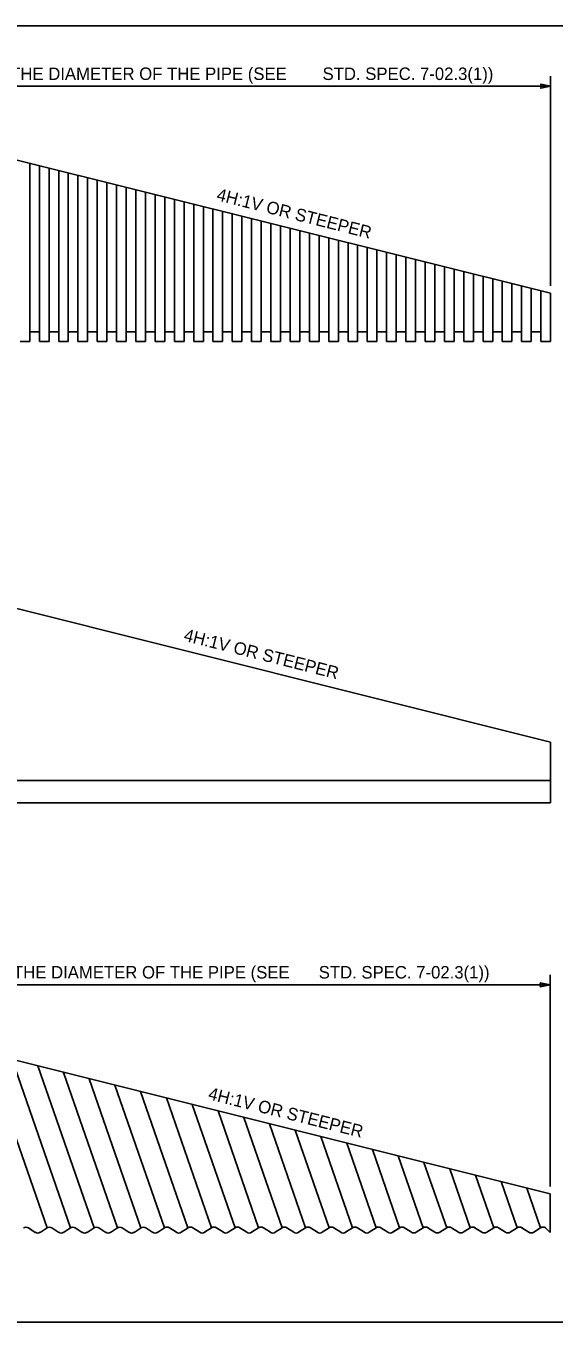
# Model space of a CAD drawing. Extents: x 99862 to 103680, y 99470 to 102076.
# Drawn here: x 101176 to 102021, y 100000 to 102076 of the extents above; entities that cross this region are included whole.
import ezdxf

# ---------------------------------------------------------------- set-up
doc = ezdxf.new("R2010")
doc.units = 0
for name, color, linetype in [('Default', 7, 'Continuous'), ('Level 1', 7, 'Continuous'), ('Level 15', 7, 'Continuous'), ('Level 20', 7, 'Continuous'), ('Level 5', 7, 'Continuous'), ('Level 6', 7, 'Continuous')]:
    doc.layers.add(name, color=color, linetype=linetype)

msp = doc.modelspace()

# ---------------------------------------------------------------- linework, layer by layer
at = {"layer": 'Default'}
for points in [[(102015.5, 101978.9), (101999.8, 101982), (102000.5, 101978.9), (101999.8, 101975.8)], [(102014.8, 100539.8), (101999.1, 100542.9), (101999.8, 100539.8), (101999.1, 100536.7)]]:
    msp.add_lwpolyline(points, close=True, dxfattribs=at)
at = {"layer": 'Level 1'}
msp.add_lwpolyline([(99862, 99999.5), (103151, 99999.5), (103151, 102075.5), (99862, 102075.5)], close=True, dxfattribs=at)
at = {"layer": 'Level 15'}
for p, q in [((102015.5, 101659.4), (102015.5, 101994.9)), ((100348, 101978.9), (102015.5, 101978.9)), ((102014.8, 100216.9), (102014.8, 100555.8)), ((100347.3, 100539.8), (102014.8, 100539.8))]:
    msp.add_line(p, q, dxfattribs=at)
at = {"layer": 'Level 5'}
for p, q in [((101150.9, 101863.4), (102015.5, 101647.3)), ((101181.8, 101570.1), (101181.8, 101855.7)), ((101197.2, 101570.1), (101197.2, 101851.9)), ((101212.6, 101570.1), (101212.6, 101848)), ((101228.1, 101570.1), (101228.1, 101844.1)), ((101243.5, 101570.1), (101243.5, 101840.3)), ((101259, 101570.1), (101259, 101836.4)), ((101274.4, 101570.1), (101274.4, 101832.6)), ((101289.8, 101570.1), (101289.8, 101828.7)), ((101305.3, 101570.1), (101305.3, 101824.8)), ((101320.7, 101570.1), (101320.7, 101821)), ((101336.2, 101570.1), (101336.2, 101817.1)), ((101351.6, 101570.1), (101351.6, 101813.3)), ((101367, 101570.1), (101367, 101809.4)), ((101382.5, 101570.1), (101382.5, 101805.5)), ((101397.9, 101570.1), (101397.9, 101801.7)), ((101413.4, 101570.1), (101413.4, 101797.8)), ((101428.8, 101570.1), (101428.8, 101794)), ((101444.2, 101570.1), (101444.2, 101790.1)), ((101459.7, 101570.1), (101459.7, 101786.2)), ((101475.1, 101570.1), (101475.1, 101782.4)), ((101490.6, 101570.1), (101490.6, 101778.5)), ((101506, 101570.1), (101506, 101774.7)), ((101521.4, 101570.1), (101521.4, 101770.8)), ((101536.9, 101570.1), (101536.9, 101766.9)), ((101552.3, 101570.1), (101552.3, 101763.1)), ((101567.8, 101570.1), (101567.8, 101759.2)), ((101583.2, 101570.1), (101583.2, 101755.4)), ((101598.6, 101570.1), (101598.6, 101751.5)), ((101614.1, 101570.1), (101614.1, 101747.6)), ((101629.5, 101570.1), (101629.5, 101743.8)), ((101645, 101570.1), (101645, 101739.9)), ((101660.4, 101570.1), (101660.4, 101736.1)), ((101675.8, 101570.1), (101675.8, 101732.2)), ((101691.3, 101570.1), (101691.3, 101728.3)), ((101706.7, 101570.1), (101706.7, 101724.5)), ((101722.2, 101570.1), (101722.2, 101720.6)), ((101737.6, 101570.1), (101737.6, 101716.8)), ((101753, 101570.1), (101753, 101712.9)), ((101768.5, 101570.1), (101768.5, 101709)), ((101783.9, 101570.1), (101783.9, 101705.2)), ((101799.4, 101570.1), (101799.4, 101701.3)), ((101814.8, 101570.1), (101814.8, 101697.5)), ((101830.2, 101570.1), (101830.2, 101693.6)), ((101845.7, 101570.1), (101845.7, 101689.7)), ((101861.1, 101570.1), (101861.1, 101685.9)), ((101876.6, 101570.1), (101876.6, 101682)), ((101892, 101570.1), (101892, 101678.2)), ((101907.4, 101570.1), (101907.4, 101674.3)), ((101922.9, 101570.1), (101922.9, 101670.4)), ((101938.3, 101570.1), (101938.3, 101666.6)), ((101953.8, 101570.1), (101953.8, 101662.7)), ((101969.2, 101570.1), (101969.2, 101658.9)), ((101984.6, 101570.1), (101984.6, 101655)), ((102000.1, 101570.1), (102000.1, 101651.1)), ((102015.5, 101570.1), (102015.5, 101647.3)), ((101197.2, 101585.5), (101181.8, 101585.5)), ((101228.1, 101585.5), (101212.6, 101585.5)), ((101259, 101585.5), (101243.5, 101585.5)), ((101274.4, 101585.5), (101289.8, 101585.5)), ((101305.3, 101585.5), (101320.7, 101585.5)), ((101336.2, 101585.5), (101351.6, 101585.5)), ((101367, 101585.5), (101382.5, 101585.5)), ((101397.9, 101585.5), (101413.4, 101585.5)), ((101428.8, 101585.5), (101444.2, 101585.5)), ((101459.7, 101585.5), (101475.1, 101585.5)), ((101490.6, 101585.5), (101506, 101585.5)), ((101521.4, 101585.5), (101536.9, 101585.5)), ((101552.3, 101585.5), (101567.8, 101585.5)), ((101583.2, 101585.5), (101598.6, 101585.5)), ((101614.1, 101585.5), (101629.5, 101585.5)), ((101645, 101585.5), (101660.4, 101585.5)), ((101675.8, 101585.5), (101691.3, 101585.5)), ((101706.7, 101585.5), (101722.2, 101585.5)), ((101737.6, 101585.5), (101753, 101585.5)), ((101768.5, 101585.5), (101783.9, 101585.5)), ((101799.4, 101585.5), (101814.8, 101585.5)), ((101830.2, 101585.5), (101845.7, 101585.5)), ((101861.1, 101585.5), (101876.6, 101585.5)), ((101892, 101585.5), (101907.4, 101585.5)), ((101922.9, 101585.5), (101938.3, 101585.5)), ((101953.8, 101585.5), (101969.2, 101585.5)), ((101984.6, 101585.5), (102000.1, 101585.5))]:
    msp.add_line(p, q, dxfattribs=at)
at = {"layer": 'Level 6'}
for p, q in [((101181.8, 101570.1), (101166.3, 101570.1)), ((101212.6, 101570.1), (101197.2, 101570.1)), ((101243.5, 101570.1), (101228.1, 101570.1)), ((101274.4, 101570.1), (101259, 101570.1)), ((101305.3, 101570.1), (101289.8, 101570.1)), ((101336.2, 101570.1), (101320.7, 101570.1)), ((101367, 101570.1), (101351.6, 101570.1)), ((101397.9, 101570.1), (101382.5, 101570.1)), ((101428.8, 101570.1), (101413.4, 101570.1)), ((101459.7, 101570.1), (101444.2, 101570.1)), ((101490.6, 101570.1), (101475.1, 101570.1)), ((101521.4, 101570.1), (101506, 101570.1)), ((101552.3, 101570.1), (101536.9, 101570.1)), ((101583.2, 101570.1), (101567.8, 101570.1)), ((101614.1, 101570.1), (101598.6, 101570.1)), ((101645, 101570.1), (101629.5, 101570.1)), ((101675.8, 101570.1), (101660.4, 101570.1)), ((101706.7, 101570.1), (101691.3, 101570.1)), ((101737.6, 101570.1), (101722.2, 101570.1)), ((101768.5, 101570.1), (101753, 101570.1)), ((101799.4, 101570.1), (101783.9, 101570.1)), ((101830.2, 101570.1), (101814.8, 101570.1)), ((101861.1, 101570.1), (101845.7, 101570.1)), ((101892, 101570.1), (101876.6, 101570.1)), ((101922.9, 101570.1), (101907.4, 101570.1)), ((101953.8, 101570.1), (101938.3, 101570.1)), ((101984.6, 101570.1), (101969.2, 101570.1)), ((102015.5, 101570.1), (102000.1, 101570.1)), ((101009, 101180.1), (102015.5, 100928.5)), ((102015.5, 100831.2), (102015.5, 100928.5)), ((99961.8, 100866.7), (102015.5, 100866.7)), ((100401, 100831.2), (102015.5, 100831.2)), ((101104.8, 100432.3), (102014.8, 100204.8)), ((101112.3, 100430.4), (101209.5, 100150.3)), ((101153.5, 100420.1), (101247.1, 100150.3)), ((101194.7, 100409.8), (101284.7, 100150.3)), ((101235.9, 100399.5), (101322.3, 100150.3)), ((101276.9, 100389.3), (101359.8, 100150.2)), ((101318.1, 100379), (101397.4, 100150.2)), ((101359.3, 100368.7), (101435, 100150.2)), ((101400.5, 100358.4), (101472.7, 100150.2)), ((101442, 100348), (101510.6, 100150.4)), ((101483.2, 100337.7), (101548.2, 100150.4)), ((101524.4, 100327.4), (101585.8, 100150.4)), ((101565.6, 100317.1), (101623.4, 100150.4)), ((101606.8, 100306.8), (101661, 100150.4)), ((101648, 100296.5), (101698.6, 100150.4)), ((101689.2, 100286.2), (101736.3, 100150.4)), ((101730.4, 100275.9), (101773.9, 100150.4)), ((101771.7, 100265.5), (101811.6, 100150.5)), ((101812.9, 100255.3), (101849.3, 100150.5)), ((101854.1, 100245), (101886.9, 100150.5)), ((101895.3, 100234.7), (101924.5, 100150.5)), ((101936.5, 100224.4), (101962.1, 100150.5)), ((101977.7, 100214.1), (101999.7, 100150.5)), ((102014.8, 100143), (102014.8, 100204.8)), ((101179.5, 100150.3), (101190.7, 100143.2)), ((101198.3, 100143.2), (101209.5, 100150.3)), ((101217.1, 100150.3), (101228.3, 100143.2)), ((101235.9, 100143.2), (101247.1, 100150.3)), ((101254.7, 100150.3), (101265.9, 100143.2)), ((101273.5, 100143.2), (101284.7, 100150.3)), ((101292.3, 100150.3), (101303.5, 100143.2)), ((101311.1, 100143.2), (101322.3, 100150.3)), ((101329.9, 100150.3), (101341.1, 100143.2)), ((101348.7, 100143.2), (101359.9, 100150.3)), ((101367.6, 100150.3), (101378.7, 100143.2)), ((101386.4, 100143.2), (101397.6, 100150.3)), ((101405.3, 100150.4), (101416.5, 100143.3)), ((101435.3, 100150.4), (101424.1, 100143.3)), ((101442.9, 100150.4), (101454.1, 100143.3)), ((101472.9, 100150.4), (101461.7, 100143.3)), ((101480.6, 100150.4), (101491.7, 100143.3)), ((101510.6, 100150.4), (101499.4, 100143.3)), ((101518.2, 100150.4), (101529.4, 100143.3)), ((101548.2, 100150.4), (101537, 100143.3)), ((101555.8, 100150.4), (101567, 100143.3)), ((101574.6, 100143.3), (101585.8, 100150.4)), ((101593.4, 100150.4), (101604.6, 100143.3)), ((101612.2, 100143.3), (101623.4, 100150.4)), ((101631, 100150.4), (101642.2, 100143.3)), ((101649.8, 100143.3), (101661, 100150.4)), ((101668.6, 100150.4), (101679.8, 100143.3)), ((101687.5, 100143.3), (101698.6, 100150.4)), ((101706.3, 100150.4), (101717.5, 100143.3)), ((101725.1, 100143.3), (101736.3, 100150.4)), ((101743.9, 100150.4), (101755.1, 100143.3)), ((101762.7, 100143.3), (101773.9, 100150.4)), ((101774, 100150.5), (101762.8, 100143.3)), ((101781.6, 100150.5), (101792.8, 100143.3)), ((101800.4, 100143.3), (101811.6, 100150.5)), ((101819.3, 100150.5), (101830.4, 100143.3)), ((101838.1, 100143.3), (101849.3, 100150.5)), ((101856.9, 100150.5), (101868.1, 100143.3)), ((101875.7, 100143.3), (101886.9, 100150.5)), ((101894.5, 100150.5), (101905.7, 100143.3)), ((101913.3, 100143.3), (101924.5, 100150.5)), ((101932.1, 100150.5), (101943.3, 100143.3)), ((101950.8, 100143.3), (101962, 100150.4)), ((101950.9, 100143.3), (101962.1, 100150.5)), ((101969.7, 100150.5), (101980.9, 100143.3)), ((101988.5, 100143.3), (101999.7, 100150.5)), ((102007.5, 100150.6), (102014.8, 100143))]:
    msp.add_line(p, q, dxfattribs=at)
for centre, start, end in [((101175.7, 100144.4), 56, 124), ((101213.3, 100144.4), 56, 124), ((101250.9, 100144.4), 56, 124), ((101288.5, 100144.4), 56, 124), ((101326.1, 100144.4), 56, 124), ((101363.7, 100144.4), 56, 124), ((101401.5, 100144.5), 56, 124), ((101439.1, 100144.5), 56, 124), ((101476.7, 100144.5), 56, 124), ((101514.4, 100144.5), 56, 124), ((101552, 100144.5), 56, 124), ((101589.6, 100144.5), 56, 124), ((101627.2, 100144.5), 56, 124), ((101664.8, 100144.5), 56, 124), ((101702.5, 100144.5), 56, 124), ((101740.1, 100144.5), 56, 124), ((101777.8, 100144.6), 56, 124), ((101815.4, 100144.6), 56, 124), ((101853.1, 100144.6), 56, 124), ((101890.7, 100144.6), 56, 124), ((101928.3, 100144.6), 56, 124), ((101965.9, 100144.6), 56, 124), ((102003.7, 100144.7), 56, 124), ((101194.5, 100149.1), 236, 304), ((101232.1, 100149.1), 236, 304), ((101269.7, 100149.1), 236, 304), ((101307.3, 100149.1), 236, 304), ((101344.9, 100149.1), 236, 304), ((101382.6, 100149.1), 236, 304), ((101420.3, 100149.2), 236, 304), ((101457.9, 100149.2), 236, 304), ((101495.6, 100149.2), 236, 304), ((101533.2, 100149.2), 236, 304), ((101570.8, 100149.2), 236, 304), ((101608.4, 100149.2), 236, 304), ((101646, 100149.2), 236, 304), ((101683.6, 100149.2), 236, 304), ((101721.3, 100149.2), 236, 304), ((101758.9, 100149.2), 236, 304), ((101796.6, 100149.3), 236, 304), ((101834.3, 100149.3), 236, 304), ((101871.9, 100149.3), 236, 304), ((101909.5, 100149.3), 236, 304), ((101947.1, 100149.3), 236, 304), ((101984.7, 100149.3), 236, 304)]:
    msp.add_arc(centre, 7.05, start, end, dxfattribs=at)

# ---------------------------------------------------------------- texts
at = {"layer": 'Level 20'}
for s, p in [('END SECTION LENGTH SHALL BE AT LEAST SIX TIMES THE DIAMETER OF THE PIPE (SEE ', (100435.6, 101988.9)), ('STD. SPEC. 7-02.3(1))', (101650.5, 101988.9)), ('END SECTION LENGTH SHALL BE AT LEAST SIX TIMES THE DIAMETER OF THE PIPE (SEE', (100440.1, 100549.8)), (' STD. SPEC. 7-02.3(1))', (101637, 100549.8))]:
    msp.add_text(s, height=20, dxfattribs=at).set_placement(p)
for p in [(101479.6, 101796.5), (101427.1, 101091), (101466.2, 100356.6)]:
    msp.add_text('4H:1V OR STEEPER', height=20, rotation=345.8652, dxfattribs=at).set_placement(p)

doc.saveas('drawing.dxf')
